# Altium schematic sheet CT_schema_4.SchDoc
size 388 x 258 mm
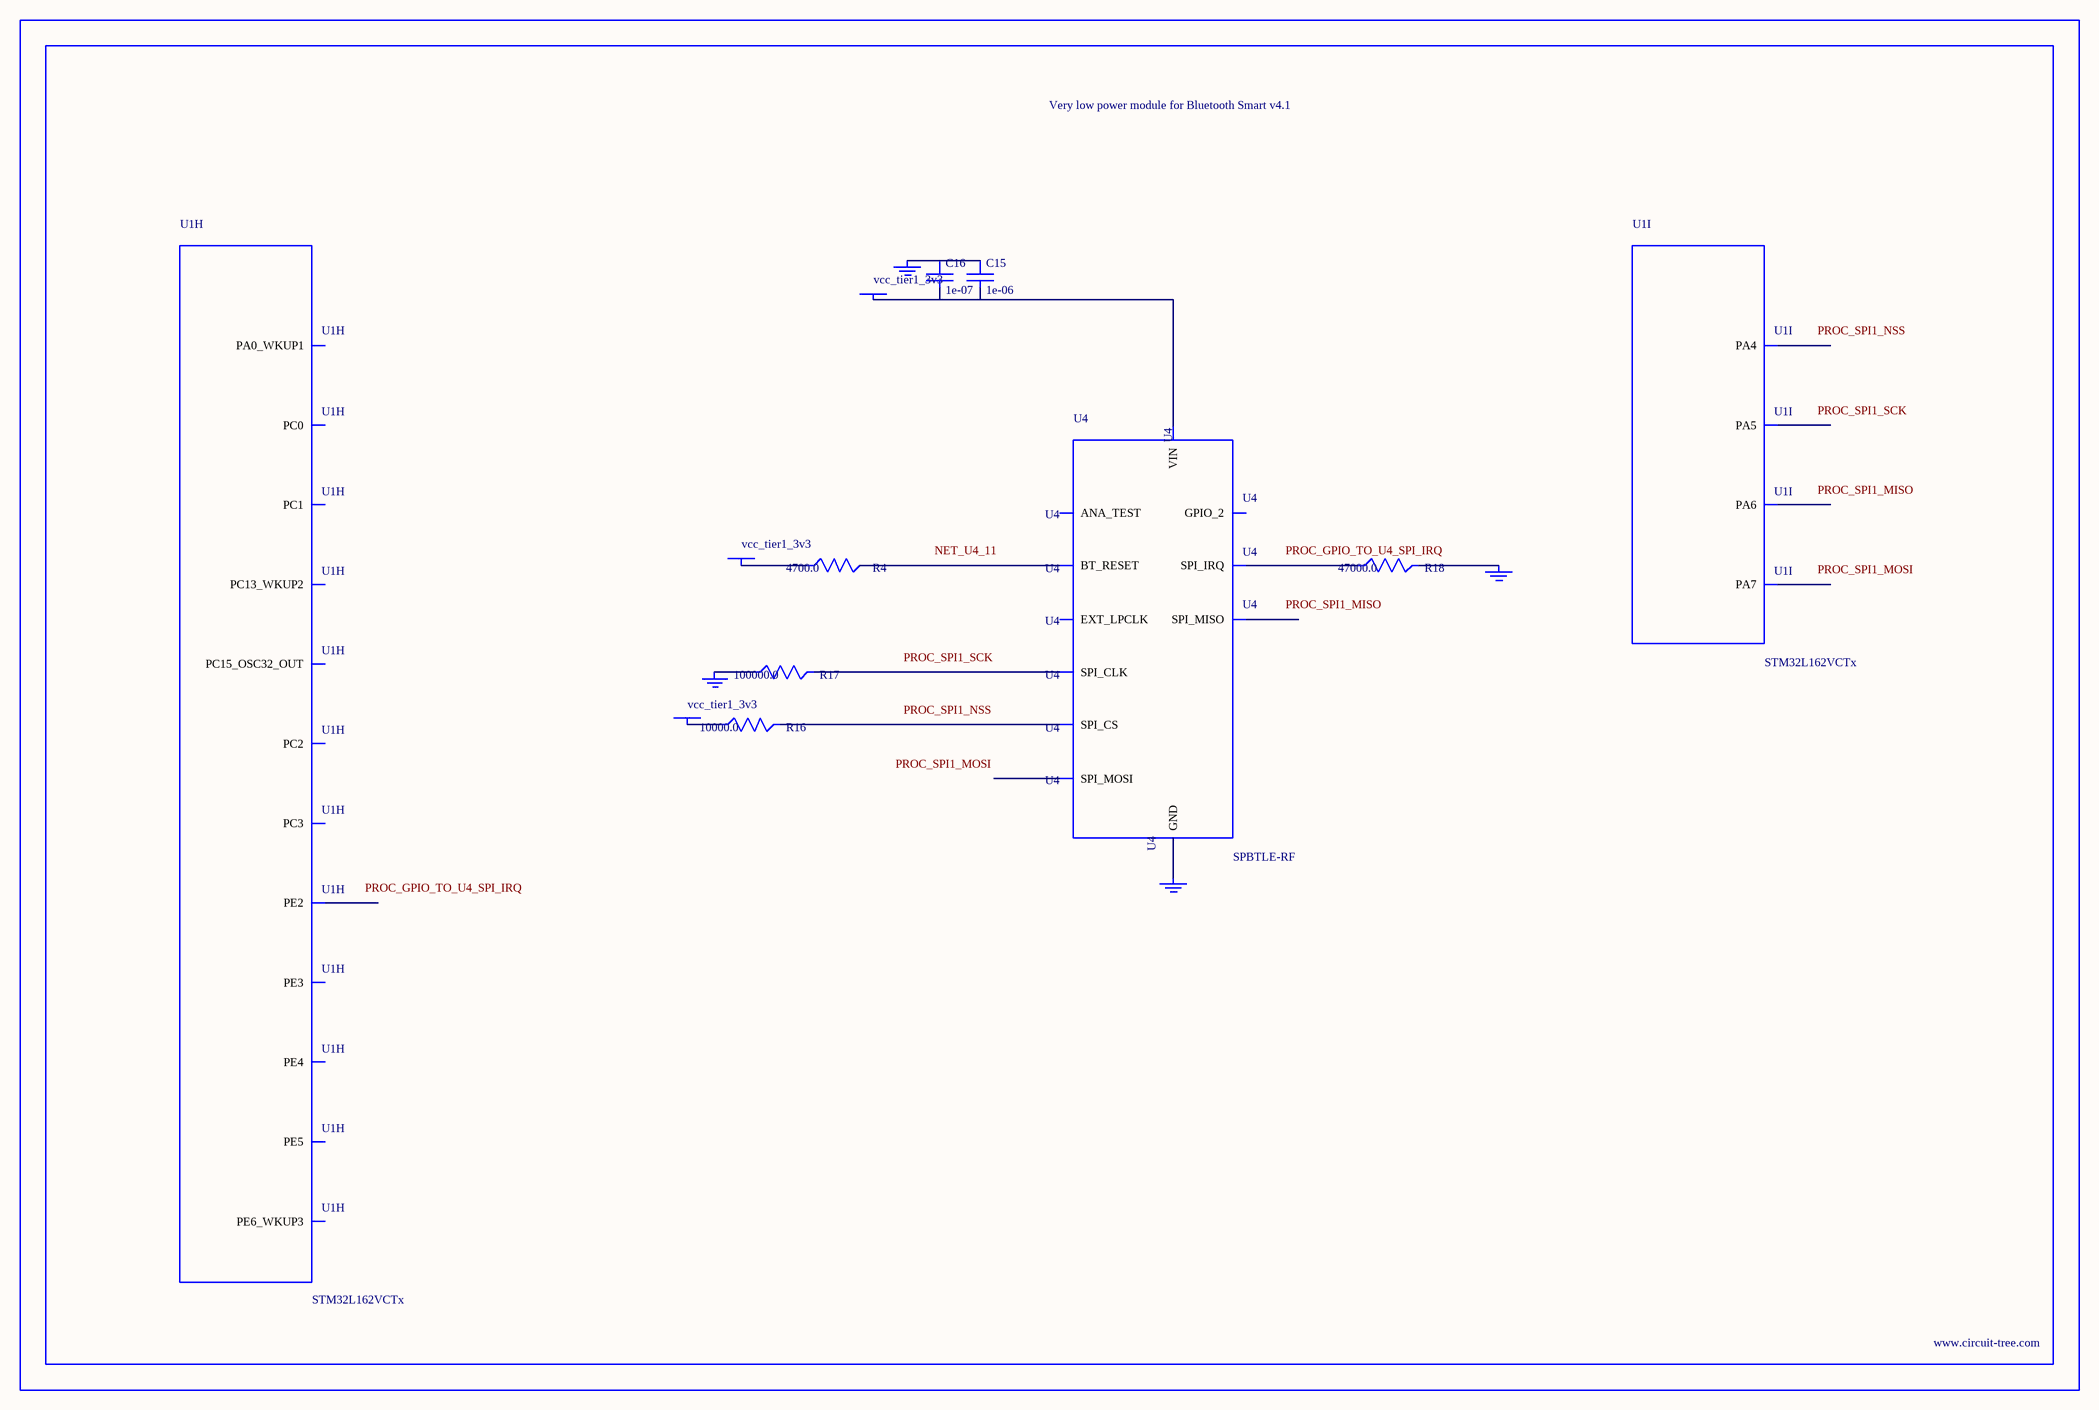
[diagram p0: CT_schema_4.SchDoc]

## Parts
BORDER3  (no value)
C15  1e-06  [C0603]
C16  1e-07  [C0402]
GND_INSTANCE_3_0  (no value)
GND_INSTANCE_3_1  (no value)
GND_INSTANCE_3_2  (no value)
GND_INSTANCE_3_3  (no value)
POWER_INSTANCE_3_0  vcc_tier1_3v3
POWER_INSTANCE_3_1  vcc_tier1_3v3
POWER_INSTANCE_3_2  vcc_tier1_3v3
R4  4700.0  [R0603]
R16  10000.0  [R0603]
R17  100000.0  [R0603]
R18  47000.0  [R0603]
U1  STM32L162VCTx  [LQFP100]  (parts H,I of 11)
U4  SPBTLE-RF  [XCVR_SPBTLE-RF]

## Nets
NetC15_1: C15.1 C16.1 GND_INSTANCE_3_1.0(GND)
NetC15_2: C15.2 C16.2 POWER_INSTANCE_3_0.0(PWR) U4.5(VIN)
NetGND_INSTANCE_3_0_0: GND_INSTANCE_3_0.0(GND) R18.2
NetGND_INSTANCE_3_2_0: GND_INSTANCE_3_2.0(GND) R17.1
NetGND_INSTANCE_3_3_0: GND_INSTANCE_3_3.0(GND) U4.6(GND)
NetPOWER_INSTANCE_3_1_0: POWER_INSTANCE_3_1.0(PWR) R16.1
NetPOWER_INSTANCE_3_2_0: POWER_INSTANCE_3_2.0(PWR) R4.1
NetR4_2: R4.2 U4.11(BT_RESET)
NetR16_2: R16.2 U4.10(SPI_CS)
NetR17_2: R17.2 U4.7(SPI_CLK)
NetR18_1: R18.1 U4.4(SPI_IRQ)

Not connected (* = marked no-connect by the designer): U1 1(PE2) 2(PE3) 3(PE4) 4(PE5) 5(PE6_WKUP3) 7(PC13_WKUP2) 9(PC15_OSC32_OUT) 15(PC0) 16(PC1) 17(PC2) 18(PC3) 23(PA0_WKUP1) 29(PA4) 30(PA5) 31(PA6) 32(PA7); U4 1(EXT_LPCLK) 2(GPIO_2) 3(ANA_TEST) 8(SPI_MISO) 9(SPI_MOSI)

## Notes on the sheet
- Labels drawn without touching a wire or pin: NET_U4_11, PROC_GPIO_TO_U4_SPI_IRQ, PROC_SPI1_MISO, PROC_SPI1_MOSI, PROC_SPI1_NSS, PROC_SPI1_SCK

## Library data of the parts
BORDER3 = BORDER_PAGE3
C15 = C0603C105K3RACTU
C16 = C0402C104K3RACTU
GND_INSTANCE_3_0-GND_INSTANCE_3_3 = GND
POWER_INSTANCE_3_0-POWER_INSTANCE_3_2 = PWR
R4 = RC0603JR-074K7L
R16 = RC0603JR-0710KL
R17 = RC0603JR-07100KL
R18 = RC0603JR-0747KL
